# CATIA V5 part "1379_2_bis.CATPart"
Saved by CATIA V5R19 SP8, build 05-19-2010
Part number: 2_bis
Bounding box of the stored display mesh (mm): x -8.948 to 8.948, y -8.948 to 8.948, z 37.701 to 87.701
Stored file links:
  C:\Users\ThinkMotion\Desktop\EU_thinkMotion\iao\IAO_MMS_Groupe3\bblot\bblot\1379_2_bis.CATPart
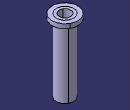
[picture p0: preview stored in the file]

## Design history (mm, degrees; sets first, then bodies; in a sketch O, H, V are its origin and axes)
Body1 (main body)
  Sketch1 on yz-plane, origin (0, 0, 0), H (0, 1, 0), V (0, 0, 1)
    line L1 (-2.5, 40.7007) -> (-2.5, 37.7007)
    line L2 (-2.5, 37.7007) -> (-6, 37.7007)
    line L3 (-6, 37.7007) -> (-6, 84.7007)
    point P4 (-6, 87.7007)
    line L4 (-6, 87.7007) -> (-4, 87.7007)
    line L5 (-4, 87.7007) -> (-4, 40.7007)
    line L6 (-4, 40.7007) -> (-2.5, 40.7007)
    axis line L7 (0, 87.7007) -> (0, 37.7007)
    point P7 (0, 87.7007)
    point P8 (0, 37.7007)
    line L8 (-6, 87.7007) -> (-9, 87.7007)
    line L9 (-9, 87.7007) -> (-9, 84.7007)
    line L10 (-9, 84.7007) -> (-6, 84.7007)
    distance L7 L3 = 6
    length L4 = 2
    distance L7 L1 = 2.5
    length L1 = 3
    distance L2 P4 = 50
    length L9 = 3
    length L10 = 3
    distance L3 L5 = 2
    vertical: L1 V, L3 V, L5 V, L7 V, L9 V
    horizontal: L2 H, L4 H, L6 H, L8 H, L10 H
    coincidence: P7 V, P7 L4, P8 L2
  Shaft1: profile Sketch1, axis Sketch1.L7, angle 360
